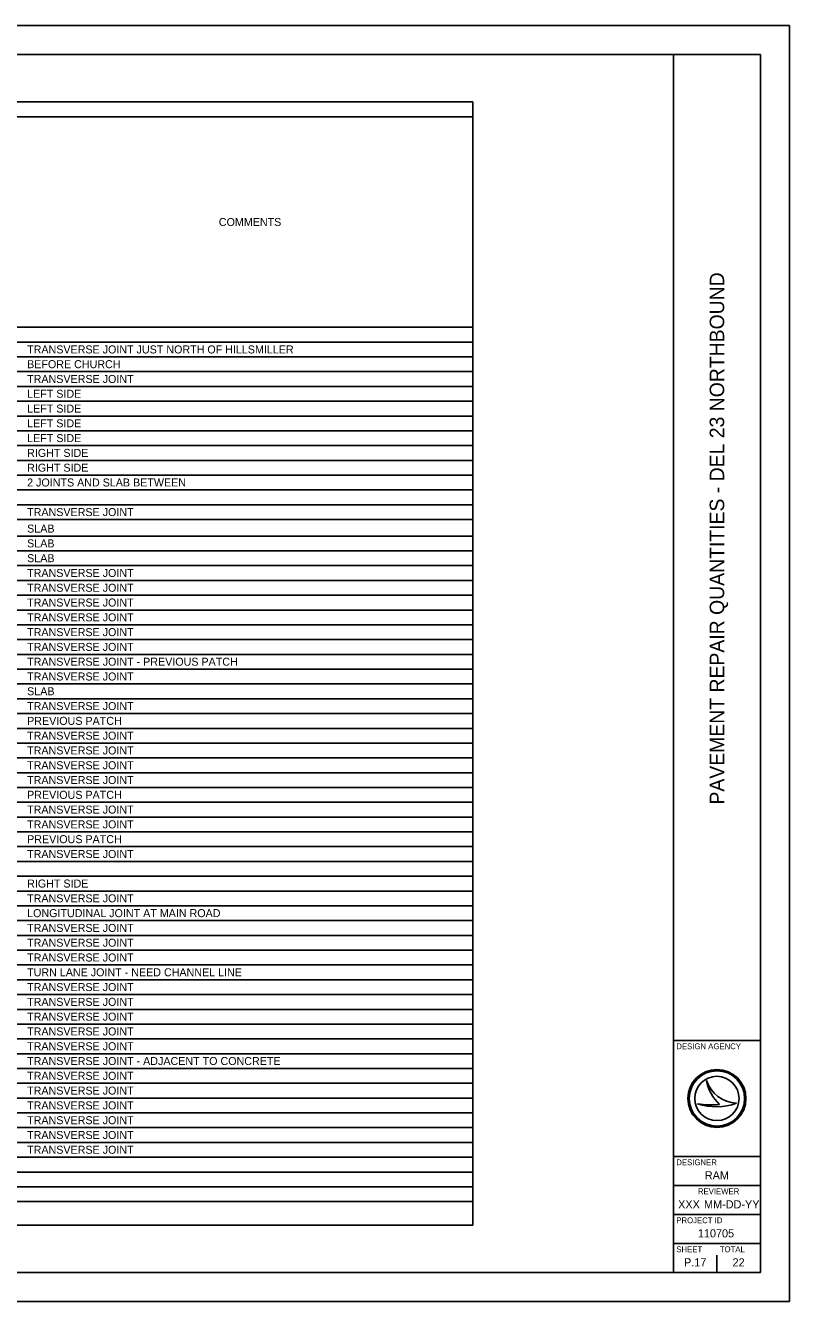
# Model space of a CAD drawing. Extents: x 0 to 34, y 0 to 22.
# Drawn here: x 20.83 to 34, y 0 to 22 of the extents above; entities that cross this region are included whole.
import ezdxf

# ---------------------------------------------------------------- set-up
doc = ezdxf.new("R2010")
doc.units = 0
for name, color, linetype in [('Default', 7, 'Continuous'), ('SH_Border', 7, 'Continuous'), ('SH_Cut_Line', 7, 'Continuous'), ('SH_Data', 7, 'Continuous')]:
    doc.layers.add(name, color=color, linetype=linetype)

msp = doc.modelspace()

# ---------------------------------------------------------------- linework, layer by layer
at = {"layer": 'Default'}
for p, q in [((5.007, 20.682), (28.542, 20.682)), ((28.542, 20.682), (28.542, 1.317)), ((5.007, 20.427), (28.542, 20.427)), ((5.007, 16.797), (28.542, 16.797)), ((5.007, 16.542), (28.542, 16.542)), ((5.007, 16.287), (28.542, 16.287)), ((5.007, 16.032), (28.542, 16.032)), ((5.007, 15.777), (28.542, 15.777)), ((5.007, 15.522), (28.542, 15.522)), ((5.007, 15.267), (28.542, 15.267)), ((5.007, 15.012), (28.542, 15.012)), ((5.007, 14.757), (28.542, 14.757)), ((5.007, 14.502), (28.542, 14.502)), ((5.007, 14.247), (28.542, 14.247)), ((5.007, 13.992), (28.542, 13.992)), ((5.007, 13.737), (28.542, 13.737)), ((5.007, 13.482), (28.542, 13.482)), ((5.007, 13.197), (28.542, 13.197)), ((5.007, 12.942), (28.542, 12.942)), ((5.007, 12.687), (28.542, 12.687)), ((5.007, 12.432), (28.542, 12.432)), ((5.007, 12.177), (28.542, 12.177)), ((5.007, 11.922), (28.542, 11.922)), ((5.007, 11.667), (28.542, 11.667)), ((5.007, 11.412), (28.542, 11.412)), ((5.007, 11.157), (28.542, 11.157)), ((5.007, 10.902), (28.542, 10.902)), ((5.007, 10.647), (28.542, 10.647)), ((5.007, 10.392), (28.542, 10.392)), ((5.007, 10.137), (28.542, 10.137)), ((5.007, 9.882), (28.542, 9.882)), ((5.007, 9.627), (28.542, 9.627)), ((5.007, 9.372), (28.542, 9.372)), ((5.007, 9.117), (28.542, 9.117)), ((5.007, 8.862), (28.542, 8.862)), ((5.007, 8.607), (28.542, 8.607)), ((5.007, 8.352), (28.542, 8.352)), ((5.007, 8.097), (28.542, 8.097)), ((5.007, 7.842), (28.542, 7.842)), ((5.007, 7.587), (28.542, 7.587)), ((5.007, 7.332), (28.542, 7.332)), ((5.007, 7.077), (28.542, 7.077)), ((5.007, 6.822), (28.542, 6.822)), ((5.007, 6.567), (28.542, 6.567)), ((5.007, 6.312), (28.542, 6.312)), ((5.007, 6.057), (28.542, 6.057)), ((5.007, 5.802), (28.542, 5.802)), ((5.007, 5.547), (28.542, 5.547)), ((5.007, 5.292), (28.542, 5.292)), ((5.007, 5.037), (28.542, 5.037)), ((5.007, 4.782), (28.542, 4.782)), ((5.007, 4.527), (28.542, 4.527)), ((5.007, 4.272), (28.542, 4.272)), ((5.007, 4.017), (28.542, 4.017)), ((5.007, 3.762), (28.542, 3.762)), ((5.007, 3.507), (28.542, 3.507)), ((5.007, 3.252), (28.542, 3.252)), ((5.007, 2.997), (28.542, 2.997)), ((5.007, 2.742), (28.542, 2.742)), ((5.007, 2.487), (28.542, 2.487)), ((5.007, 2.232), (28.542, 2.232)), ((5.007, 1.977), (28.542, 1.977)), ((5.007, 1.722), (28.542, 1.722)), ((5.007, 1.317), (28.542, 1.317))]:
    msp.add_line(p, q, dxfattribs=at)
at = {"layer": 'SH_Border'}
for p, q in [((32, 0.5), (32, 21.5)), ((32, 4.5), (33.5, 4.5)), ((32, 2.5), (33.5, 2.5)), ((32, 2), (33.5, 2)), ((32, 1.5), (33.5, 1.5)), ((32, 1), (33.5, 1))]:
    msp.add_line(p, q, dxfattribs=at)
msp.add_lwpolyline([(1.5, 21.5), (33.5, 21.5), (33.5, 0.5), (1.5, 0.5)], close=True, dxfattribs=at)
at = {"layer": 'SH_Cut_Line'}
msp.add_lwpolyline([(0, 0), (34, 0), (34, 22), (0, 22)], close=True, dxfattribs=at)
at = {"layer": 'SH_Data'}
for p, q in [((32.567, 3.81), (32.567, 3.81)), ((32.417, 3.41), (32.417, 3.41)), ((32.75, 3.5), (32.75, 3.5)), ((33.087, 3.419), (33.087, 3.419)), ((32.375, 0.675), (32.375, 0.675)), ((32.75, 0.5), (32.75, 0.8))]:
    msp.add_line(p, q, dxfattribs=at)
for radius in [0.5, 0.477, 0.477, 0.382]:
    msp.add_circle((32.75, 3.5), radius, dxfattribs=at)
for centre, radius, start, end in [((33.116, 3.998), 0.58, 198.9257, 198.9319), ((33.347, 3.97), 0.796, 191.6379, 191.6421), ((33.116, 3.998), 0.58, 198.9319, 267.1657), ((33.347, 3.97), 0.796, 191.6421, 226.0947), ((32.739, 4.37), 1.013, 251.4576, 290.0832), ((32.648, 4.654), 1.266, 259.4964, 259.4995), ((32.739, 4.37), 1.013, 251.4527, 251.4576), ((32.648, 4.654), 1.266, 259.4995, 276.6672)]:
    msp.add_arc(centre, radius, start, end, dxfattribs=at)

# ---------------------------------------------------------------- texts
at = {"layer": 'Default'}
for s, p in [('COMMENTS', (24.166, 18.543)), ('TRANSVERSE JOINT JUST NORTH OF HILLSMILLER', (20.862, 16.346)), ('BEFORE CHURCH', (20.862, 16.092)), ('TRANSVERSE JOINT', (20.862, 15.837)), ('LEFT SIDE', (20.862, 15.582)), ('LEFT SIDE', (20.862, 15.327)), ('LEFT SIDE', (20.862, 15.072)), ('LEFT SIDE', (20.862, 14.817)), ('RIGHT SIDE', (20.862, 14.562)), ('RIGHT SIDE', (20.862, 14.307)), ('2 JOINTS AND SLAB BETWEEN', (20.862, 14.052)), ('TRANSVERSE JOINT', (20.862, 13.542)), ('SLAB', (20.862, 13.257)), ('SLAB', (20.862, 13.002)), ('SLAB', (20.862, 12.747)), ('TRANSVERSE JOINT', (20.862, 12.492)), ('TRANSVERSE JOINT', (20.862, 12.237)), ('TRANSVERSE JOINT', (20.862, 11.982)), ('TRANSVERSE JOINT', (20.862, 11.727)), ('TRANSVERSE JOINT', (20.862, 11.472)), ('TRANSVERSE JOINT', (20.862, 11.217)), ('TRANSVERSE JOINT - PREVIOUS PATCH', (20.862, 10.962)), ('TRANSVERSE JOINT', (20.862, 10.707)), ('SLAB', (20.862, 10.452)), ('TRANSVERSE JOINT', (20.862, 10.197)), ('PREVIOUS PATCH', (20.862, 9.942)), ('TRANSVERSE JOINT', (20.862, 9.687)), ('TRANSVERSE JOINT', (20.862, 9.432)), ('TRANSVERSE JOINT', (20.862, 9.177)), ('TRANSVERSE JOINT', (20.862, 8.922)), ('PREVIOUS PATCH', (20.862, 8.667)), ('TRANSVERSE JOINT', (20.862, 8.412)), ('TRANSVERSE JOINT', (20.862, 8.157)), ('PREVIOUS PATCH', (20.862, 7.902)), ('TRANSVERSE JOINT', (20.862, 7.647)), ('RIGHT SIDE', (20.862, 7.137)), ('TRANSVERSE JOINT', (20.862, 6.882)), ('LONGITUDINAL JOINT AT MAIN ROAD', (20.862, 6.627)), ('TRANSVERSE JOINT', (20.862, 6.372)), ('TRANSVERSE JOINT', (20.862, 6.117)), ('TRANSVERSE JOINT', (20.862, 5.862)), ('TURN LANE JOINT - NEED CHANNEL LINE', (20.862, 5.607)), ('TRANSVERSE JOINT', (20.862, 5.352)), ('TRANSVERSE JOINT', (20.862, 5.097)), ('TRANSVERSE JOINT', (20.862, 4.842)), ('TRANSVERSE JOINT', (20.862, 4.587)), ('TRANSVERSE JOINT', (20.862, 4.332)), ('TRANSVERSE JOINT - ADJACENT TO CONCRETE', (20.862, 4.077)), ('TRANSVERSE JOINT', (20.862, 3.822)), ('TRANSVERSE JOINT', (20.862, 3.567)), ('TRANSVERSE JOINT', (20.862, 3.312)), ('TRANSVERSE JOINT', (20.862, 3.057)), ('TRANSVERSE JOINT', (20.862, 2.802)), ('TRANSVERSE JOINT', (20.862, 2.547))]:
    msp.add_text(s, height=0.138, dxfattribs=at).set_placement(p)
at = {"layer": 'SH_Data'}
msp.add_text('PAVEMENT REPAIR QUANTITIES - DEL 23 NORTHBOUND', height=0.25, rotation=90, dxfattribs=at).set_placement((32.875, 8.568))
for s, height, p in [('DESIGN AGENCY', 0.1, (32.05, 4.35)), ('DESIGNER', 0.1, (32.05, 2.35)), ('RAM', 0.14, (32.541, 2.105)), ('REVIEWER', 0.1, (32.422, 1.85)), ('XXX', 0.14, (32.081, 1.605)), ('MM-DD-YY', 0.14, (32.527, 1.605)), ('PROJECT ID', 0.1, (32.05, 1.35)), ('110705', 0.14, (32.421, 1.105)), ('SHEET', 0.1, (32.05, 0.85)), ('TOTAL', 0.1, (32.8, 0.85)), ('P.17', 0.14, (32.183, 0.605)), ('22', 0.14, (33.019, 0.605))]:
    msp.add_text(s, height=height, dxfattribs=at).set_placement(p)

doc.saveas('drawing.dxf')
